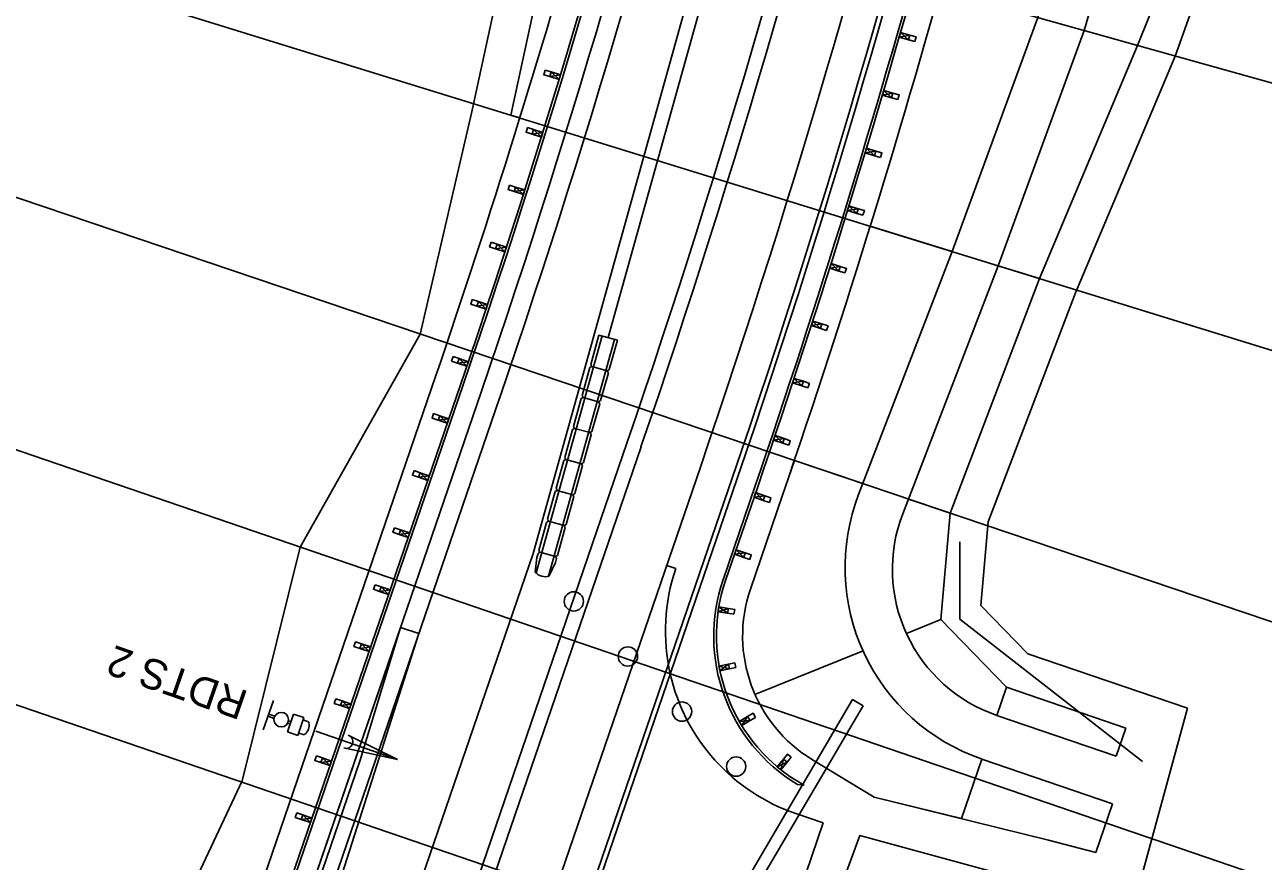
# Model space of a CAD drawing. Extents: x 157201 to 163282, y 424960 to 427200.
# Drawn here: x 157340.7 to 157469, y 426339.6 to 426426.3 of the extents above; entities that cross this region are included whole.
import ezdxf

# ---------------------------------------------------------------- set-up
doc = ezdxf.new("R2010")
doc.units = 0
for name, color, linetype in [('BD_X_Building', 7, 'Continuous'), ('Default', 7, 'Continuous'), ('GE_P_Alignment', 7, 'Continuous'), ('PM_X_Stop_Line', 7, 'Continuous'), ('PV_X_Shoulder', 7, 'Continuous'), ('PV_X_Text', 7, 'Continuous'), ('RD_X_Cells', 7, 'Continuous'), ('RD_X_Gate', 7, 'Continuous'), ('RW_X_CL_100_Curve_Data', 7, 'Continuous'), ('RW_X_CL_100_Distances', 7, 'Continuous'), ('RW_X_CL_100_Stations', 7, 'Continuous'), ('SC_Scratch1', 7, 'Continuous'), ('SN_X_Public', 7, 'Continuous'), ('UT_X_Electric', 7, 'Continuous'), ('UT_X_Sanitary_Cells', 7, 'Continuous')]:
    doc.layers.add(name, color=color, linetype=linetype)

msp = doc.modelspace()

# ---------------------------------------------------------------- linework, layer by layer
at = {"layer": 'BD_X_Building'}
for p, q in [((157420.42, 426381.1), (157419.2, 426377.5)), ((157420.42, 426381.1), (157427.51, 426378.71)), ((157419.2, 426377.5), (157415.87, 426367.78)), ((157422.29, 426350.09), (157428.68, 426346.22)), ((157437.75, 426343.98), (157439.86, 426350.16)), ((157437.75, 426343.98), (157428.68, 426346.22))]:
    msp.add_line(p, q, dxfattribs=at)
msp.add_arc((157430.06, 426362.92), 15, 161.0943, 238.818, dxfattribs=at)
at = {"layer": 'Default'}
for p, q in [((157300.71, 426467.71), (157531.78, 426402.84)), ((157294.53, 426446.74), (157523.82, 426375.84)), ((157287.8, 426425.95), (157515.15, 426349.07)), ((157279.85, 426402.74), (157506.91, 426324.97)), ((157271.75, 426379.09), (157498.81, 426301.32))]:
    msp.add_line(p, q, dxfattribs=at)
at = {"layer": 'GE_P_Alignment'}
for points in [[(157387.98, 426388.19), (157355.02, 426291.96), (157348.94, 426273.14)], [(157414.47, 426379.12), (157381.59, 426283.12), (157358.98, 426213.15)]]:
    msp.add_lwpolyline(points, dxfattribs=at)
for radius in [942, 970]:
    msp.add_arc((156496.79, 426693.41), radius, 341.09435, 351.99348, dxfattribs=at)
at = {"layer": 'PM_X_Stop_Line'}
for p, q in [((157407.19, 426370.22), (157408.14, 426369.9)), ((157420.58, 426344.5), (157423.41, 426343.53)), ((157418.23, 426328.39), (157423.41, 426343.53))]:
    msp.add_line(p, q, dxfattribs=at)
for start, end in [(161.0943, 192.8827), (192.8827, 251.0943)]:
    msp.add_arc((157427.06, 426363.42), 20, start, end, dxfattribs=at)
at = {"layer": 'PV_X_Shoulder'}
for p, q in [((157441.4, 426354.68), (157453.78, 426350.44)), ((157439.86, 426350.16), (157453.37, 426345.53))]:
    msp.add_line(p, q, dxfattribs=at)
for points in [[(157427.07, 426377.57), (157436.77, 426402.76), (157445.64, 426427.02), (157453.59, 426454.31)], [(157431.65, 426375.56), (157441.55, 426401.28), (157450.45, 426425.67), (157458.93, 426454.79)]]:
    msp.add_lwpolyline(points, dxfattribs=at)
for centre, radius, start in [((157446.67, 426370.02), 21, 158.9323), ((157446.58, 426369.82), 16, 158.9481)]:
    msp.add_arc(centre, radius, start, 251.0943, dxfattribs=at)
at = {"layer": 'PV_X_Text'}
for p, q in [((157437.57, 426364.67), (157437.57, 426372.67)), ((157456.48, 426349.9), (157437.57, 426364.67))]:
    msp.add_line(p, q, dxfattribs=at)
at = {"layer": 'RD_X_Cells'}
for p, q in [((157431.29, 426424.99), (157432.39, 426425.19)), ((157431.43, 426425.47), (157432.25, 426424.71)), ((157429.68, 426419.46), (157430.5, 426418.7)), ((157429.54, 426418.98), (157430.64, 426419.18)), ((157427.76, 426412.99), (157428.86, 426413.18)), ((157427.9, 426413.47), (157428.72, 426412.7)), ((157425.94, 426407.01), (157427.04, 426407.2)), ((157426.08, 426407.49), (157426.89, 426406.72)), ((157424.23, 426401.52), (157425.03, 426400.74)), ((157424.08, 426401.04), (157425.18, 426401.22)), ((157422.18, 426395.09), (157423.28, 426395.26)), ((157422.33, 426395.56), (157423.13, 426394.78)), ((157420.24, 426389.14), (157421.35, 426389.31)), ((157420.4, 426389.62), (157421.19, 426388.83)), ((157418.42, 426383.69), (157419.21, 426382.89)), ((157418.26, 426383.21), (157419.37, 426383.37)), ((157413.03, 426368.75), (157416.36, 426378.47)), ((157416.62, 426378.38), (157413.29, 426368.66)), ((157416.25, 426377.29), (157417.36, 426377.44)), ((157416.41, 426377.77), (157417.2, 426376.97)), ((157414.23, 426371.38), (157415.33, 426371.53)), ((157414.39, 426371.85), (157415.17, 426371.06)), ((157412.52, 426365.43), (157413.58, 426365.77)), ((157412.59, 426365.93), (157413.5, 426365.28)), ((157412.61, 426359.8), (157413.69, 426359.5)), ((157412.71, 426359.31), (157413.59, 426359.99)), ((157414.71, 426354.05), (157415.83, 426354.14)), ((157414.97, 426353.62), (157415.57, 426354.57)), ((157418.65, 426349.36), (157419.67, 426349.82)), ((157419.03, 426349.05), (157419.28, 426350.14)), ((157421.42, 426347.45), (157420.74, 426347.52))]:
    msp.add_line(p, q, dxfattribs=at)
for points in [[(157432.25, 426424.71), (157432.39, 426425.19), (157431.43, 426425.47), (157431.29, 426424.99)], [(157432.89, 426424.53), (157433.03, 426425.01), (157432.39, 426425.19), (157432.25, 426424.71)], [(157430.5, 426418.7), (157430.64, 426419.18), (157429.68, 426419.46), (157429.54, 426418.98)], [(157431.14, 426418.51), (157431.28, 426418.99), (157430.64, 426419.18), (157430.5, 426418.7)], [(157428.72, 426412.7), (157428.86, 426413.18), (157427.9, 426413.47), (157427.76, 426412.99)], [(157429.35, 426412.51), (157429.5, 426412.99), (157428.86, 426413.18), (157428.72, 426412.7)], [(157426.89, 426406.72), (157427.04, 426407.2), (157426.08, 426407.49), (157425.94, 426407.01)], [(157427.53, 426406.52), (157427.68, 426407), (157427.04, 426407.2), (157426.89, 426406.72)], [(157425.03, 426400.74), (157425.18, 426401.22), (157424.23, 426401.52), (157424.08, 426401.04)], [(157425.66, 426400.54), (157425.82, 426401.02), (157425.18, 426401.22), (157425.03, 426400.74)], [(157423.13, 426394.78), (157423.28, 426395.26), (157422.33, 426395.56), (157422.18, 426395.09)], [(157423.76, 426394.58), (157423.92, 426395.05), (157423.28, 426395.26), (157423.13, 426394.78)], [(157421.19, 426388.83), (157421.35, 426389.31), (157420.4, 426389.62), (157420.24, 426389.14)], [(157421.82, 426388.62), (157421.98, 426389.1), (157421.35, 426389.31), (157421.19, 426388.83)], [(157419.21, 426382.89), (157419.37, 426383.37), (157418.42, 426383.69), (157418.26, 426383.21)], [(157419.84, 426382.68), (157420, 426383.15), (157419.37, 426383.37), (157419.21, 426382.89)], [(157417.2, 426376.97), (157417.36, 426377.44), (157416.41, 426377.77), (157416.25, 426377.29)], [(157417.83, 426376.75), (157417.99, 426377.23), (157417.36, 426377.44), (157417.2, 426376.97)], [(157415.17, 426371.06), (157415.33, 426371.53), (157414.39, 426371.85), (157414.23, 426371.38)], [(157415.8, 426370.84), (157415.96, 426371.31), (157415.33, 426371.53), (157415.17, 426371.06)], [(157413.5, 426365.28), (157413.58, 426365.77), (157412.59, 426365.93), (157412.52, 426365.43)], [(157414.16, 426365.17), (157414.24, 426365.67), (157413.58, 426365.77), (157413.5, 426365.28)], [(157413.69, 426359.5), (157413.59, 426359.99), (157412.61, 426359.8), (157412.71, 426359.31)], [(157414.34, 426359.63), (157414.25, 426360.12), (157413.59, 426359.99), (157413.69, 426359.5)], [(157415.83, 426354.14), (157415.57, 426354.57), (157414.71, 426354.05), (157414.97, 426353.62)], [(157416.4, 426354.48), (157416.14, 426354.91), (157415.57, 426354.57), (157415.83, 426354.14)], [(157420.09, 426350.34), (157419.7, 426350.65), (157419.28, 426350.14), (157419.67, 426349.82)], [(157419.67, 426349.82), (157419.28, 426350.14), (157418.65, 426349.36), (157419.03, 426349.05)]]:
    msp.add_lwpolyline(points, close=True, dxfattribs=at)
for centre, radius, start, end in [((156496.79, 426693.41), 972, 341.09435, 348.22537), ((156496.79, 426693.41), 972.28, 341.09435, 348.22532), ((157430.06, 426362.92), 18, 161.0943, 238.818), ((157430.06, 426362.92), 17.72, 161.0943, 240.8297)]:
    msp.add_arc(centre, radius, start, end, dxfattribs=at)
at = {"layer": 'RD_X_Gate'}
for p, q in [((157455.99, 426424.11), (157450.45, 426425.67)), ((157391.97, 426416.61), (157391.03, 426416.9)), ((157428.28, 426405.39), (157436.77, 426402.76)), ((157445.83, 426399.96), (157441.55, 426401.28)), ((157420.42, 426381.1), (157427.51, 426378.71)), ((157419.2, 426377.5), (157415.87, 426367.78)), ((157436.55, 426375.65), (157432.24, 426377.1)), ((157435.61, 426364.61), (157432.03, 426363.17)), ((157416.34, 426356.85), (157427.54, 426361.36)), ((157442.41, 426357.61), (157441.41, 426354.68)), ((157454.78, 426353.37), (157453.78, 426350.44)), ((157422.29, 426350.09), (157428.68, 426346.22)), ((157451.64, 426340.47), (157453.37, 426345.53))]:
    msp.add_line(p, q, dxfattribs=at)
for points in [[(157454.78, 426353.37), (157442.41, 426357.61), (157435.61, 426364.61), (157436.55, 426375.65), (157445.83, 426399.96), (157455.99, 426424.11), (157465.8, 426448.53), (157467.16, 426461.66), (157465.74, 426477.55)], [(157391.03, 426416.9), (157396.23, 426440.89), (157393.45, 426458.13)], [(157383.25, 426389.81), (157350.27, 426293.54), (157344.74, 426276.41)], [(157428.68, 426346.22), (157446.75, 426341.75), (157451.64, 426340.47)]]:
    msp.add_lwpolyline(points, dxfattribs=at)
for centre, radius, start, end in [((156496.79, 426693.41), 975, 341.09435, 348.22537), ((156496.79, 426693.41), 937, 341.09435, 344.31767), ((157430.06, 426362.92), 15, 161.0943, 238.818)]:
    msp.add_arc(centre, radius, start, end, dxfattribs=at)
at = {"layer": 'RW_X_CL_100_Curve_Data'}
for points in [[(157389.87, 426387.55), (157356.92, 426291.33), (157350.84, 426272.52)], [(157410.68, 426380.42), (157377.79, 426284.38), (157341.03, 426170.6)]]:
    msp.add_lwpolyline(points, dxfattribs=at)
for radius in [944, 966]:
    msp.add_arc((156496.79, 426693.41), radius, 341.09435, 351.99348, dxfattribs=at)
at = {"layer": 'RW_X_CL_100_Distances'}
msp.add_line((157403.11, 426383.01), (157373.86, 426297.6), dxfattribs=at)
for points in [[(157404.53, 426382.52), (157371.62, 426286.44), (157348.99, 426216.37)], [(157358.5, 426213.3), (157381.11, 426283.28), (157413.99, 426379.28)]]:
    msp.add_lwpolyline(points, dxfattribs=at)
for radius in [958, 959.5, 969.5]:
    msp.add_arc((156496.79, 426693.41), radius, 341.09435, 351.99348, dxfattribs=at)
at = {"layer": 'RW_X_CL_100_Stations'}
for p, q in [((157409.27, 426428.62), (157393.34, 426371.45)), ((157410.79, 426428.52), (157401.13, 426393.84)), ((157393.65, 426369.47), (157400.49, 426394.02)), ((157399.32, 426391.06), (157400.17, 426394.11)), ((157402.09, 426393.57), (157400.17, 426394.11)), ((157401.77, 426393.66), (157394.93, 426369.11)), ((157401.24, 426390.52), (157402.09, 426393.57)), ((157398.42, 426387.85), (157399.23, 426390.74)), ((157399.43, 426390.85), (157399.23, 426390.74)), ((157399.32, 426391.06), (157399.43, 426390.85)), ((157401.04, 426390.41), (157399.43, 426390.85)), ((157400.35, 426387.31), (157401.15, 426390.2)), ((157401.24, 426390.52), (157401.04, 426390.41)), ((157401.04, 426390.41), (157401.15, 426390.2)), ((157397.53, 426384.64), (157398.33, 426387.53)), ((157398.54, 426387.64), (157398.33, 426387.53)), ((157398.42, 426387.85), (157398.54, 426387.64)), ((157400.14, 426387.2), (157398.54, 426387.64)), ((157399.45, 426384.1), (157400.26, 426386.99)), ((157400.35, 426387.31), (157400.14, 426387.2)), ((157400.14, 426387.2), (157400.26, 426386.99)), ((157396.63, 426381.43), (157397.44, 426384.32)), ((157397.64, 426384.43), (157397.44, 426384.32)), ((157397.53, 426384.64), (157397.64, 426384.43)), ((157399.25, 426383.99), (157397.64, 426384.43)), ((157398.56, 426380.89), (157399.36, 426383.78)), ((157399.45, 426384.1), (157399.25, 426383.99)), ((157399.25, 426383.99), (157399.36, 426383.78)), ((157395.74, 426378.22), (157396.54, 426381.11)), ((157396.75, 426381.22), (157396.54, 426381.11)), ((157396.63, 426381.43), (157396.75, 426381.22)), ((157398.35, 426380.77), (157396.75, 426381.22)), ((157397.66, 426377.68), (157398.47, 426380.57)), ((157398.56, 426380.89), (157398.35, 426380.77)), ((157398.35, 426380.77), (157398.47, 426380.57)), ((157394.84, 426375.01), (157395.65, 426377.89)), ((157395.85, 426378.01), (157395.65, 426377.89)), ((157395.74, 426378.22), (157395.85, 426378.01)), ((157397.46, 426377.56), (157395.85, 426378.01)), ((157397.57, 426377.36), (157396.77, 426374.47)), ((157397.66, 426377.68), (157397.46, 426377.56)), ((157397.46, 426377.56), (157397.57, 426377.36)), ((157393.95, 426371.79), (157394.75, 426374.68)), ((157394.96, 426374.8), (157394.75, 426374.68)), ((157394.84, 426375.01), (157394.96, 426374.8)), ((157396.56, 426374.35), (157394.96, 426374.8)), ((157396.68, 426374.15), (157395.87, 426371.26)), ((157396.77, 426374.47), (157396.56, 426374.35)), ((157396.56, 426374.35), (157396.68, 426374.15)), ((157393.74, 426371.05), (157393.58, 426369.54)), ((157393.74, 426371.05), (157393.86, 426371.47)), ((157394.06, 426371.59), (157393.86, 426371.47)), ((157393.95, 426371.79), (157394.06, 426371.59)), ((157395.67, 426371.14), (157394.06, 426371.59)), ((157395.87, 426371.26), (157395.67, 426371.14)), ((157395.67, 426371.14), (157395.78, 426370.94)), ((157395.78, 426370.94), (157395.67, 426370.52)), ((157395.67, 426370.52), (157395.02, 426369.14)), ((157379.62, 426363.81), (157375.4, 426349.93))]:
    msp.add_line(p, q, dxfattribs=at)
for points in [[(157342.32, 426218.53), (157364.98, 426288.65), (157393.34, 426371.45)], [(157375.4, 426349.93), (157355.49, 426291.81), (157332.81, 426221.6)]]:
    msp.add_lwpolyline(points, dxfattribs=at)
for centre in [(157397.57, 426366.5), (157403.17, 426360.79), (157408.78, 426355.08), (157414.39, 426349.38)]:
    msp.add_circle(centre, 1, dxfattribs=at)
msp.add_arc((157394.6, 426370.4), 1.34, 220.2547, 288.6061, dxfattribs=at)
at = {"layer": 'SC_Scratch1'}
for p, q in [((157365.39, 426353.17), (157366.45, 426356.23)), ((157365.88, 426354.59), (157366.51, 426354.37)), ((157365.96, 426354.81), (157366.59, 426354.6)), ((157367.89, 426352.99), (157368.53, 426354.82)), ((157368, 426354.11), (157368.25, 426354.02)), ((157369.61, 426354.45), (157368.53, 426354.82)), ((157368.98, 426352.61), (157369.61, 426354.45)), ((157369.99, 426354.05), (157369.54, 426354.21)), ((157368.98, 426352.61), (157367.89, 426352.99)), ((157367.92, 426353.88), (157368.17, 426353.79)), ((157369.52, 426352.69), (157369.06, 426352.85)), ((157370.84, 426353.06), (157379.29, 426350.12)), ((157374.2, 426352.63), (157379.29, 426350.12)), ((157379.29, 426350.12), (157373.74, 426351.31))]:
    msp.add_line(p, q, dxfattribs=at)
for points in [[(157459.86, 426423.03), (157468.71, 426447.8), (157471.17, 426461.63)], [(157389.5, 426457.49), (157392.16, 426441), (157386.98, 426417.12)], [(157459.86, 426423.03), (157459.69, 426422.59), (157449.54, 426398.47), (157440.49, 426374.75), (157439.75, 426366.09), (157444.62, 426361.08), (157461.15, 426355.42)], [(157369.22, 426372.13), (157381.66, 426394.21), (157386.98, 426417.12)], [(157352.46, 426325.02), (157363.19, 426347.9), (157369.22, 426372.13)], [(157406.58, 426306.22), (157420.57, 426324.19), (157427.2, 426342.23), (157455.46, 426334.53), (157461.15, 426355.42)]]:
    msp.add_lwpolyline(points, dxfattribs=at)
msp.add_circle((157367.25, 426354.24), 0.757, dxfattribs=at)
msp.add_arc((157373.97, 426351.97), 0.703, 250.7812, 70.7812, dxfattribs=at)
msp.add_ellipse((157369.76, 426353.37), major_axis=(-0.236, -0.681), ratio=0.45371, start_param=0, end_param=3.141593, dxfattribs=at)
at = {"layer": 'SN_X_Public'}
for q in [(157322, 426176.75), (157379.62, 426363.81)]:
    msp.add_line((157381.52, 426363.16), q, dxfattribs=at)
msp.add_lwpolyline([(157379.62, 426363.81), (157355.02, 426291.96), (157332.33, 426221.75)], dxfattribs=at)
at = {"layer": 'UT_X_Electric'}
for p, q in [((157396.19, 426421.09), (157395.09, 426420.9)), ((157396.04, 426420.61), (157395.23, 426421.38)), ((157394.36, 426415.11), (157393.25, 426414.93)), ((157394.21, 426414.63), (157393.4, 426415.41)), ((157392.34, 426408.67), (157391.53, 426409.45)), ((157392.49, 426409.15), (157391.38, 426408.98)), ((157390.58, 426403.2), (157389.47, 426403.03)), ((157390.42, 426402.73), (157389.63, 426403.51)), ((157388.63, 426397.26), (157387.52, 426397.11)), ((157388.47, 426396.79), (157387.68, 426397.58)), ((157386.64, 426391.34), (157385.53, 426391.19)), ((157386.48, 426390.87), (157385.69, 426391.66)), ((157384.62, 426385.43), (157383.51, 426385.28)), ((157384.46, 426384.96), (157383.67, 426385.75)), ((157382.43, 426379.04), (157381.65, 426379.84)), ((157382.59, 426379.52), (157381.48, 426379.37)), ((157380.57, 426373.6), (157379.46, 426373.45)), ((157380.41, 426373.13), (157379.62, 426373.93)), ((157378.54, 426367.69), (157377.43, 426367.54)), ((157378.38, 426367.22), (157377.6, 426368.01)), ((157376.52, 426361.78), (157375.41, 426361.63)), ((157376.35, 426361.3), (157375.57, 426362.1)), ((157374.49, 426355.86), (157373.38, 426355.72)), ((157374.33, 426355.39), (157373.55, 426356.19)), ((157372.3, 426349.48), (157371.52, 426350.28)), ((157372.47, 426349.95), (157371.36, 426349.8)), ((157370.44, 426344.04), (157369.33, 426343.89)), ((157370.28, 426343.57), (157369.5, 426344.36))]:
    msp.add_line(p, q, dxfattribs=at)
for points in [[(157394.59, 426421.57), (157394.45, 426421.09), (157395.09, 426420.9), (157395.23, 426421.38)], [(157395.23, 426421.38), (157395.09, 426420.9), (157396.04, 426420.61), (157396.19, 426421.09)], [(157392.76, 426415.61), (157392.62, 426415.13), (157393.25, 426414.93), (157393.4, 426415.41)], [(157393.4, 426415.41), (157393.25, 426414.93), (157394.21, 426414.63), (157394.36, 426415.11)], [(157390.9, 426409.65), (157390.75, 426409.18), (157391.38, 426408.98), (157391.53, 426409.45)], [(157391.53, 426409.45), (157391.38, 426408.98), (157392.34, 426408.67), (157392.49, 426409.15)], [(157388.99, 426403.72), (157388.84, 426403.24), (157389.47, 426403.03), (157389.63, 426403.51)], [(157389.63, 426403.51), (157389.47, 426403.03), (157390.42, 426402.73), (157390.58, 426403.2)], [(157387.05, 426397.79), (157386.89, 426397.32), (157387.52, 426397.11), (157387.68, 426397.58)], [(157387.68, 426397.58), (157387.52, 426397.11), (157388.47, 426396.79), (157388.63, 426397.26)], [(157385.06, 426391.88), (157384.9, 426391.4), (157385.53, 426391.19), (157385.69, 426391.66)], [(157385.69, 426391.66), (157385.53, 426391.19), (157386.48, 426390.87), (157386.64, 426391.34)], [(157383.04, 426385.97), (157382.88, 426385.5), (157383.51, 426385.28), (157383.67, 426385.75)], [(157383.67, 426385.75), (157383.51, 426385.28), (157384.46, 426384.96), (157384.62, 426385.43)], [(157381.02, 426380.06), (157380.85, 426379.58), (157381.48, 426379.37), (157381.65, 426379.84)], [(157381.65, 426379.84), (157381.48, 426379.37), (157382.43, 426379.04), (157382.59, 426379.52)], [(157378.99, 426374.14), (157378.83, 426373.67), (157379.46, 426373.45), (157379.62, 426373.93)], [(157379.62, 426373.93), (157379.46, 426373.45), (157380.41, 426373.13), (157380.57, 426373.6)], [(157376.97, 426368.23), (157376.8, 426367.76), (157377.43, 426367.54), (157377.6, 426368.01)], [(157377.6, 426368.01), (157377.43, 426367.54), (157378.38, 426367.22), (157378.54, 426367.69)], [(157374.94, 426362.32), (157374.78, 426361.84), (157375.41, 426361.63), (157375.57, 426362.1)], [(157375.57, 426362.1), (157375.41, 426361.63), (157376.35, 426361.3), (157376.52, 426361.78)], [(157372.92, 426356.4), (157372.75, 426355.93), (157373.38, 426355.72), (157373.55, 426356.19)], [(157373.55, 426356.19), (157373.38, 426355.72), (157374.33, 426355.39), (157374.49, 426355.86)], [(157370.89, 426350.49), (157370.73, 426350.02), (157371.36, 426349.8), (157371.52, 426350.28)], [(157371.52, 426350.28), (157371.36, 426349.8), (157372.3, 426349.48), (157372.47, 426349.95)], [(157368.87, 426344.58), (157368.7, 426344.11), (157369.33, 426343.89), (157369.5, 426344.36)], [(157369.5, 426344.36), (157369.33, 426343.89), (157370.28, 426343.57), (157370.44, 426344.04)]]:
    msp.add_lwpolyline(points, close=True, dxfattribs=at)
for points in [[(157385.82, 426388.93), (157352.85, 426292.68), (157347.33, 426275.58)], [(157347.59, 426275.49), (157353.12, 426292.59), (157386.08, 426388.84)]]:
    msp.add_lwpolyline(points, dxfattribs=at)
for radius in [939.72, 940]:
    msp.add_arc((156496.79, 426693.41), radius, 341.09435, 351.99348, dxfattribs=at)
at = {"layer": 'UT_X_Sanitary_Cells'}
for p, q in [((157406.21, 426321.83), (157426.46, 426356.33)), ((157407.28, 426321.2), (157427.54, 426355.69)), ((157426.46, 426356.33), (157427.54, 426355.69))]:
    msp.add_line(p, q, dxfattribs=at)

# ---------------------------------------------------------------- texts
at = {"layer": 'SC_Scratch1'}
msp.add_text('RDTS 2', height=3.125, rotation=160.7812, dxfattribs=at).set_placement((157363.98, 426357.12))

doc.saveas('drawing.dxf')
